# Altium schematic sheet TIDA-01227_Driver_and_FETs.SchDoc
size 431 x 279 mm; Date: Not shown in title block; ApprovedBy: Not shown in title block; CheckedBy: Not shown in title block; Author: Not shown in title block; CompanyName: Not shown in title block; Engineer: Not shown in title block; Organization: Not shown in title block; Address1: Not shown in title block; Address2: Not shown in title block; Address3: Not shown in title block; Address4: Not shown in title block; DocumentNumber: 4; Revision: Use project parameter SCH_Rev; SheetNumber: 4; SheetTotal: 4; PageSetup: Record=PageOptions¦CenterHorizontal=True¦CenterVertical=True¦PrintScale=1.00¦XCorrection=1.00¦YCorrection=1.00¦PrintKind=0¦BorderSize=5000000¦LeftOffset=0¦BottomOffset=0¦Orientation=2¦PaperLength=1000¦PaperWidth=1000¦Scale=100¦PaperSource=15¦PrintQuality=600¦MediaType=1¦DitherType=10¦PaperKind=Letter¦PrintScaleMode=1
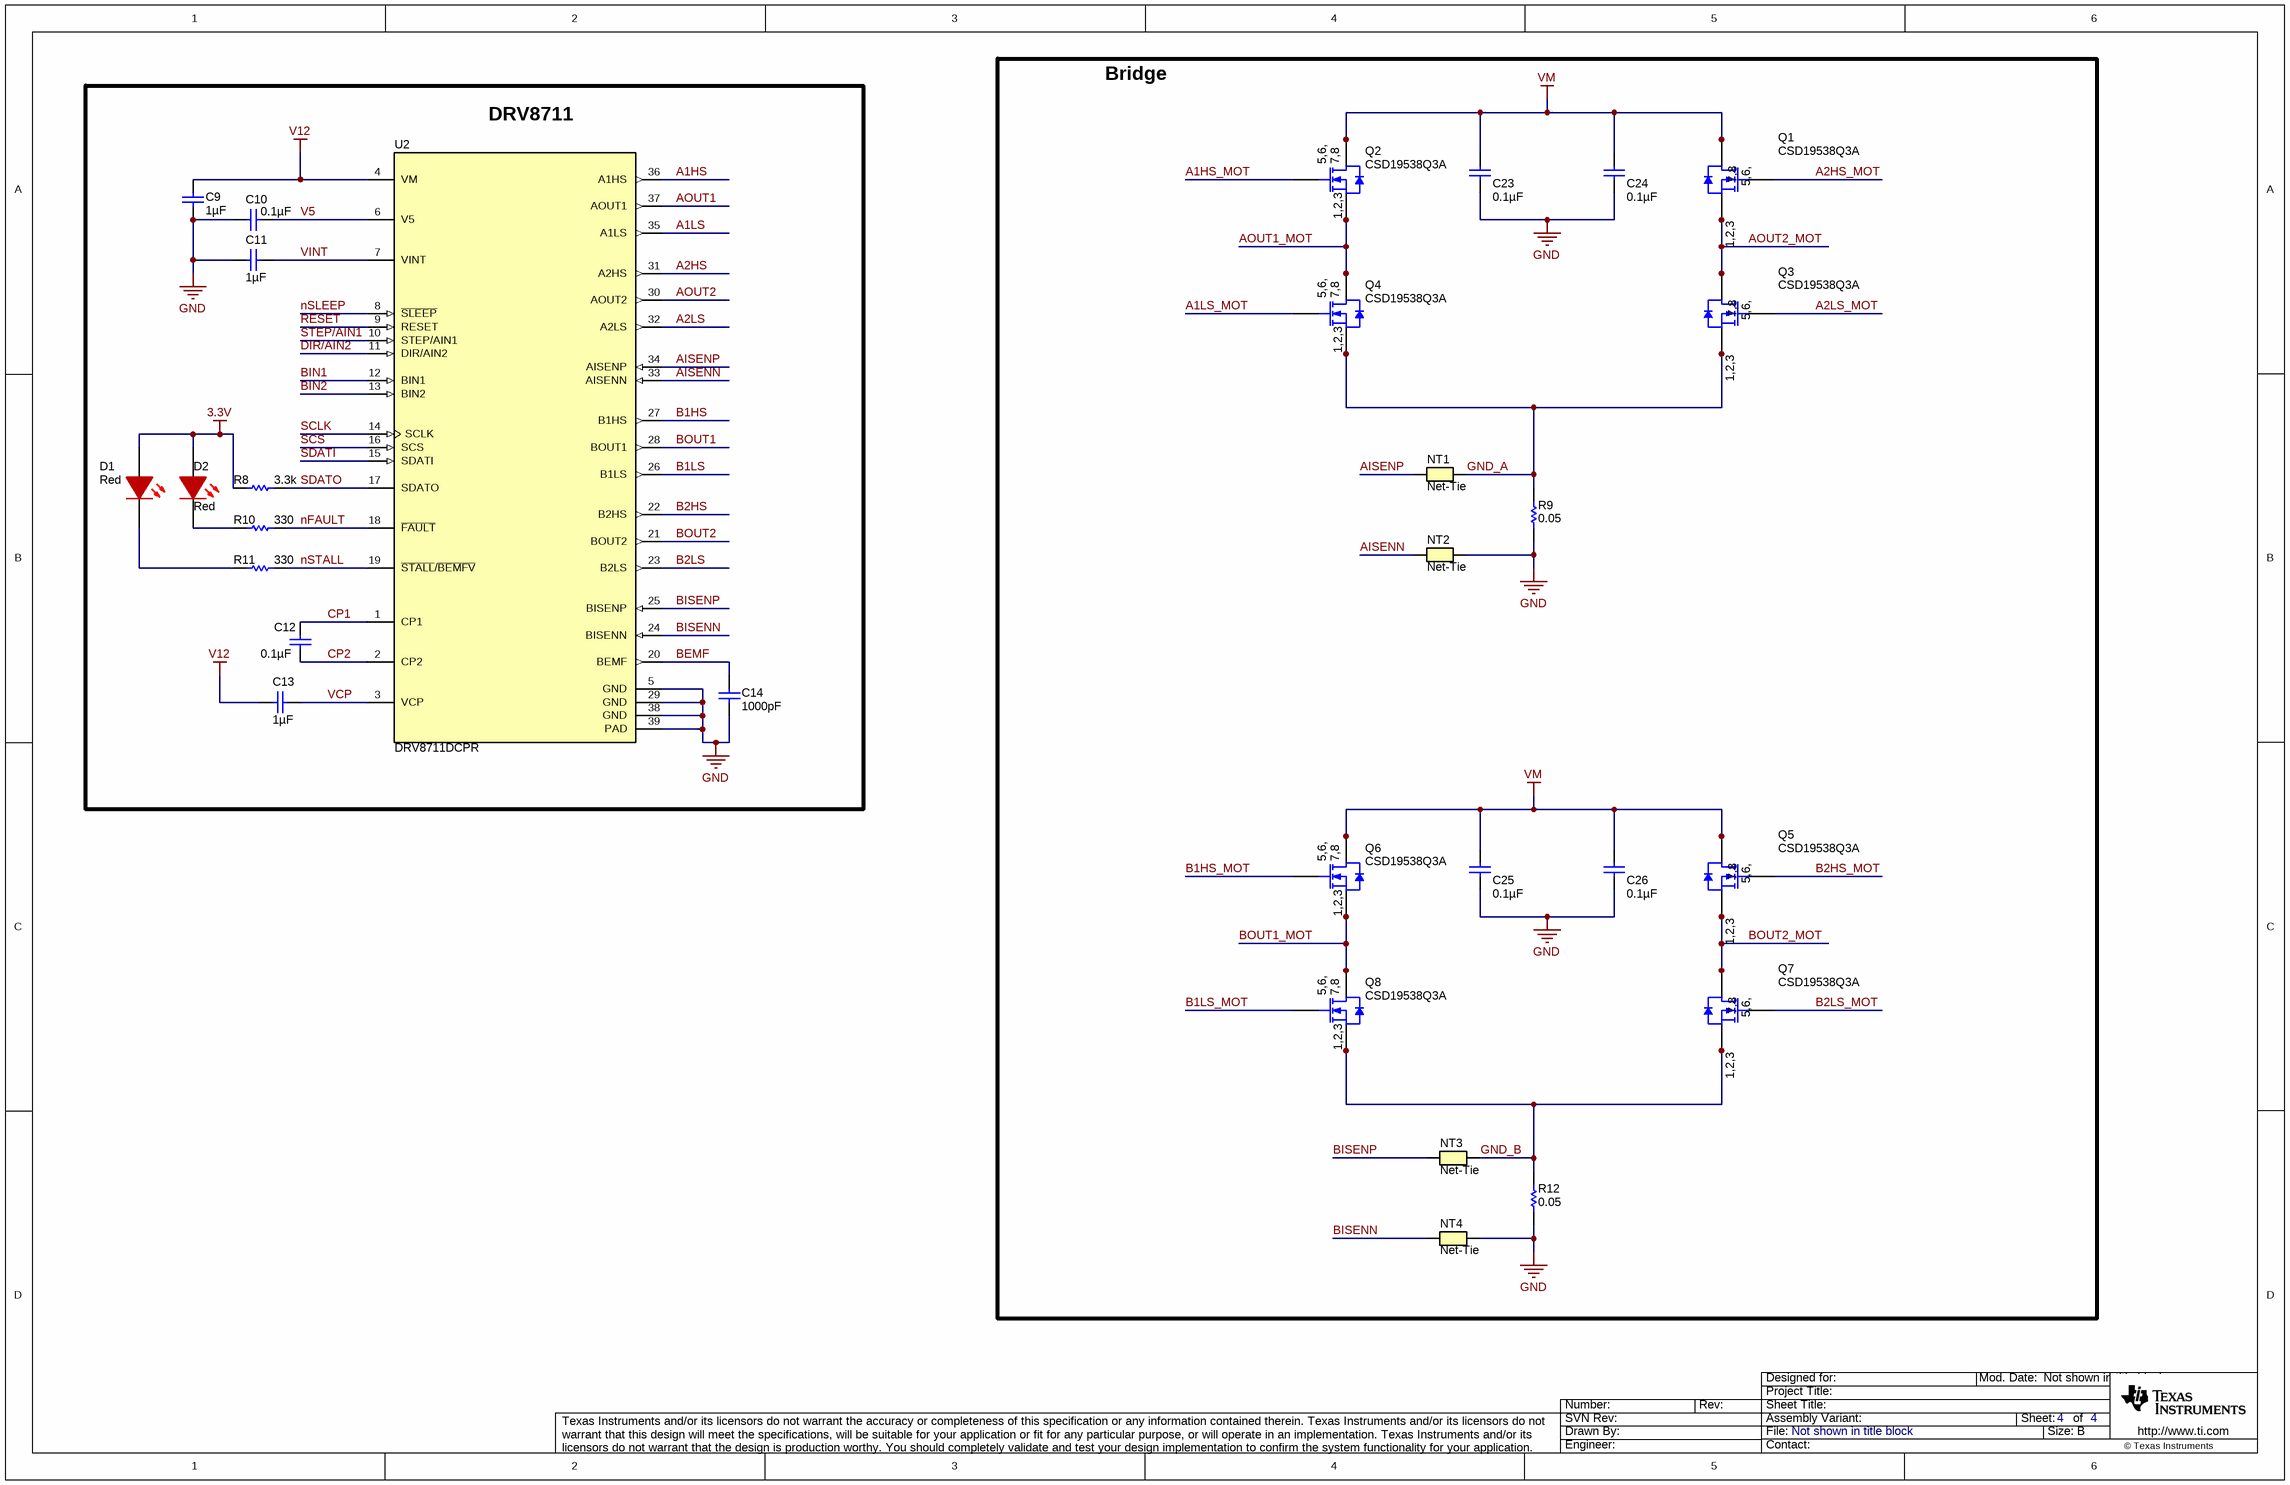
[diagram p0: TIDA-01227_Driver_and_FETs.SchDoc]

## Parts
C9  ValueDisplayed: 1µF  [0805L]  (hidden comment: GRM21BR71H105KA12L)
C10  ValueDisplayed: 0.1µF  [0603L]  (hidden comment: GRM188R72A104KA35D)
C11  ValueDisplayed: 1µF  [0603L]  (hidden comment: GRM188R71E105KA12D)
C12  ValueDisplayed: 0.1µF  [0603L]  (hidden comment: GRM188R72A104KA35D)
C13  ValueDisplayed: 1µF  [0805L]  (hidden comment: GRM21BR71H105KA12L)
C14  ValueDisplayed: 1000pF  [0603L]  (hidden comment: C0603X102K5RACTU)
C23  ValueDisplayed: 0.1µF  [0603L]  (hidden comment: GRM188R72A104KA35D)
C24  ValueDisplayed: 0.1µF  [0603L]  (hidden comment: GRM188R72A104KA35D)
C25  ValueDisplayed: 0.1µF  [0603L]  (hidden comment: GRM188R72A104KA35D)
C26  ValueDisplayed: 0.1µF  [0603L]  (hidden comment: GRM188R72A104KA35D)
D1  value Red  [WL-SMCW_RED_0805]  (hidden comment: 150080SS75000)
D2  value Red  [WL-SMCW_RED_0805]  (hidden comment: 150080SS75000)
NT1  Net-Tie  [Net-Tie_10mil]  (net tie, no BOM)
NT2  Net-Tie  [Net-Tie_10mil]  (net tie, no BOM)
NT3  Net-Tie  [Net-Tie_10mil]  (net tie, no BOM)
NT4  Net-Tie  [Net-Tie_10mil]  (net tie, no BOM)
Q1  CSD19538Q3A  [DNH0008A]
Q2  CSD19538Q3A  [DNH0008A]
Q3  CSD19538Q3A  [DNH0008A]
Q4  CSD19538Q3A  [DNH0008A]
Q5  CSD19538Q3A  [DNH0008A]
Q6  CSD19538Q3A  [DNH0008A]
Q7  CSD19538Q3A  [DNH0008A]
Q8  CSD19538Q3A  [DNH0008A]
R8  value 3.3k  [0603L]  (hidden comment: CRCW06033K30JNEA)
R9  value 0.05  [2512L]  (hidden comment: CRA2512-FZ-R050ELF)
R10  value 330  [0603L]  (hidden comment: CRCW0603330RJNEA)
R11  value 330  [0603L]  (hidden comment: CRCW0603330RJNEA)
R12  value 0.05  [2512L]  (hidden comment: CRA2512-FZ-R050ELF)
U2  DRV8711DCPR  [DCP0038A_N]

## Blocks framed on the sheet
DRV8711: C9-C14 D1 D2 R8 R10 R11 U2
Bridge: C23-C26 NT1-NT4 Q1-Q8 R9 R12

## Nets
3.3V: D1.2(A) D2.2(A) R8.2
GND: C9.2 C10.2 C11.2 C14.2 C23.2 C24.2 C25.2 C26.2 NT2.2 NT4.1 R9.1 R12.1 U2.5(GND) U2.29(GND) U2.38(GND) U2.39(PAD)
V12: C9.1 C13.2 U2.4(VM)
VM: C23.1 C24.1 C25.1 C26.1 Q1.5(D) Q1.6(D) Q1.7(D) Q1.8(D) Q1.9(D) Q2.5(D) Q2.6(D) Q2.7(D) Q2.8(D) Q2.9(D) Q5.5(D) Q5.6(D) Q5.7(D) Q5.8(D) Q5.9(D) Q6.5(D) Q6.6(D) Q6.7(D) Q6.8(D) Q6.9(D)
A1HS: U2.36(A1HS)
A1HS_MOT: Q2.4(G)
A1LS: U2.35(A1LS)
A1LS_MOT: Q4.4(G)
A2HS: U2.31(A2HS)
A2HS_MOT: Q1.4(G)
A2LS: U2.32(A2LS)
A2LS_MOT: Q3.4(G)
AISENN: NT2.1 U2.33(AISENN)
AISENP: NT1.1 U2.34(AISENP)
AOUT1: U2.37(AOUT1)
AOUT1_MOT: Q2.1(S) Q2.2(S) Q2.3(S) Q4.5(D) Q4.6(D) Q4.7(D) Q4.8(D) Q4.9(D)
AOUT2: U2.30(AOUT2)
AOUT2_MOT: Q1.1(S) Q1.2(S) Q1.3(S) Q3.5(D) Q3.6(D) Q3.7(D) Q3.8(D) Q3.9(D)
B1HS: U2.27(B1HS)
B1HS_MOT: Q6.4(G)
B1LS: U2.26(B1LS)
B1LS_MOT: Q8.4(G)
B2HS: U2.22(B2HS)
B2HS_MOT: Q5.4(G)
B2LS: U2.23(B2LS)
B2LS_MOT: Q7.4(G)
BEMF: C14.1 U2.20(BEMF)
BIN1: U2.12(BIN1)
BIN2: U2.13(BIN2)
BISENN: NT4.2 U2.24(BISENN)
BISENP: NT3.2 U2.25(BISENP)
BOUT1: U2.28(BOUT1)
BOUT1_MOT: Q6.1(S) Q6.2(S) Q6.3(S) Q8.5(D) Q8.6(D) Q8.7(D) Q8.8(D) Q8.9(D)
BOUT2: U2.21(BOUT2)
BOUT2_MOT: Q5.1(S) Q5.2(S) Q5.3(S) Q7.5(D) Q7.6(D) Q7.7(D) Q7.8(D) Q7.9(D)
CP1: C12.1 U2.1(CP1)
CP2: C12.2 U2.2(CP2)
DIR/AIN2: U2.11(DIR/AIN2)
GND_A: NT1.2 Q3.1(S) Q3.2(S) Q3.3(S) Q4.1(S) Q4.2(S) Q4.3(S) R9.2
GND_B: NT3.1 Q7.1(S) Q7.2(S) Q7.3(S) Q8.1(S) Q8.2(S) Q8.3(S) R12.2
nFAULT: R10.2 U2.18(~{FAULT})
nSLEEP: U2.8(~{SLEEP})
nSTALL: R11.1 U2.19(~{STALL}/~{BEMFV})
RESET: U2.9(RESET)
SCLK: U2.14(SCLK)
SCS: U2.16(SCS)
SDATI: U2.15(SDATI)
SDATO: R8.1 U2.17(SDATO)
STEP/AIN1: U2.10(STEP/AIN1)
V5: C10.1 U2.6(V5)
VCP: C13.1 U2.3(VCP)
VINT: C11.1 U2.7(VINT)
NetD1_1: D1.1(K) R11.2
NetD2_1: D2.1(K) R10.1

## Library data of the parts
C9 C13 = GRM21BR71H105KA12L: CAP, CERM, 1 µF, 50 V, +/- 10%, X7R, 0805; Manufacturer: MuRata; Polarized: N; CompType: Capacitor; Value: 1uF; U/M: EA; Cap_F: 0.000001; Tolerance_%: 10; Value1: Unknown; VDC_V: 50; Value2: 50V; TaMin_C: -55; TaMax_C: 125; Cap_Case: 0805; SizeArea_mm2: 2.5; SizeAreaWB_mm2: 6.75; SizeX_mm: 2; SizeY_mm: 1.25; SizeZ_mm: 1.45; AEC Category: Q200
C10 C12 C23-C26 = GRM188R72A104KA35D: CAP, CERM, 0.1uF, 100V, +/-10%, X7R, 0603; Manufacturer: MuRata; Polarized: N; CompType: Capacitor; U/M: EA; Cap_F: 0.0000001; Tolerance_%: 10; Value1: Unknown; VDC_V: 100; TaMin_C: -55; TaMax_C: 125; Cap_Case: 0603
C11 = GRM188R71E105KA12D: CAP, CERM, 1 µF, 25 V, +/- 10%, X7R, 0603; Manufacturer: MuRata; Polarized: N; CompType: Capacitor; Value: 1uF; U/M: EA; Cap_F: 0.000001; Tolerance_%: 10; Value1: Unknown; VDC_V: 25; Value2: 25V; TaMin_C: -55; TaMax_C: 125; Cap_Case: 0603; AEC Category: Q200; SizeArea_mm2: 1.28; SizeAreaWB_mm2: 4.68; SizeX_mm: 1.6; SizeY_mm: 0.8; SizeZ_mm: 1
C14 = C0603X102K5RACTU: CAP, CERM, 1000 pF, 50 V, +/- 10%, X7R, 0603; Manufacturer: Kemet; Polarized: N; CompType: Capacitor; Value: 1000pF; U/M: EA; Cap_F: 0.000000001; Tolerance_%: 10; Value1: Unknown; VDC_V: 50; Value2: 50V; TaMin_C: -55; TaMax_C: 125; Cap_Case: 0603; AEC Category: Q200; SizeArea_mm2: 1.28; SizeAreaWB_mm2: 4.68; SizeX_mm: 1.6; SizeY_mm: 0.8; SizeZ_mm: 1
D1 D2 = 150080SS75000: LED, Red, SMD; Manufacturer: Wurth Elektronik; SymbolCreator: Altium; Type: AlInGaP; Vf_V: 1.9; Value2: 1.9V; Io_A: 0.03; Vr_V: 5; Ir_A: 2.5e-005; Tjmax_C: 85; Power_TotalModule: 0.072; Value1: 0.072W; Angle: 140; U/M: EA
NT1-NT4 = Net-Tie: Single point connection between nets.; SymbolCreator: codlsc
Q1-Q8 = CSD19538Q3A: MOSFET, N-CH, 100 V, 5 A, VSONP-8; Manufacturer: Texas Instruments; Alternate Manufacturer: None; U/M: EA; ChType: N; Value: 100V; VdsMax_V: 100; Value1: ? ohm; Value2: 7.2 nC; QgTyp_nC: 7.2; Vgs_V: 20; IdsMax_A: 5; SizeAreaWB_mm2: 18.49; SizeArea_mm2: 10.89; SizeX_mm: 3.3; SizeZ_mm: 0.9; AEC Category: Q101
R8 = CRCW06033K30JNEA: RES, 3.3k ohm, 5%, 0.1W, 0603; Manufacturer: Vishay-Dale; CompType: Resistor; Res_ohm: 3300; Value_Code: 3k30; Tolerance_%: 5; Power_W: 0.1; VDC_V: 75; TempCo: 200 ppm/C; EIA_Code: E24; U/M: EA
R9 R12 = CRA2512-FZ-R050ELF: RES, 0.05 ohm, 1%, 3W, 2512; Manufacturer: Bourns; CompType: Resistor; Value_Code: R050; Tolerance_%: 1; Power_W: 3; VDC_V: 0; TempCo: 75 ppm/C; EIA_Code: E96; U/M: EA
R10 R11 = CRCW0603330RJNEA: RES, 330 ohm, 5%, 0.1W, 0603; Manufacturer: Vishay-Dale; CompType: Resistor; Value_Code: 330R; Tolerance_%: 5; Power_W: 0.1; VDC_V: 75; TempCo: 200 ppm/C; EIA_Code: E24; U/M: EA
U2 = DRV8711DCPR: STEPPER MOTOR CONTROLLER IC, DCP0038A; Manufacturer: Texas Instruments; SymbolCreator: Altum; U/M: EA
